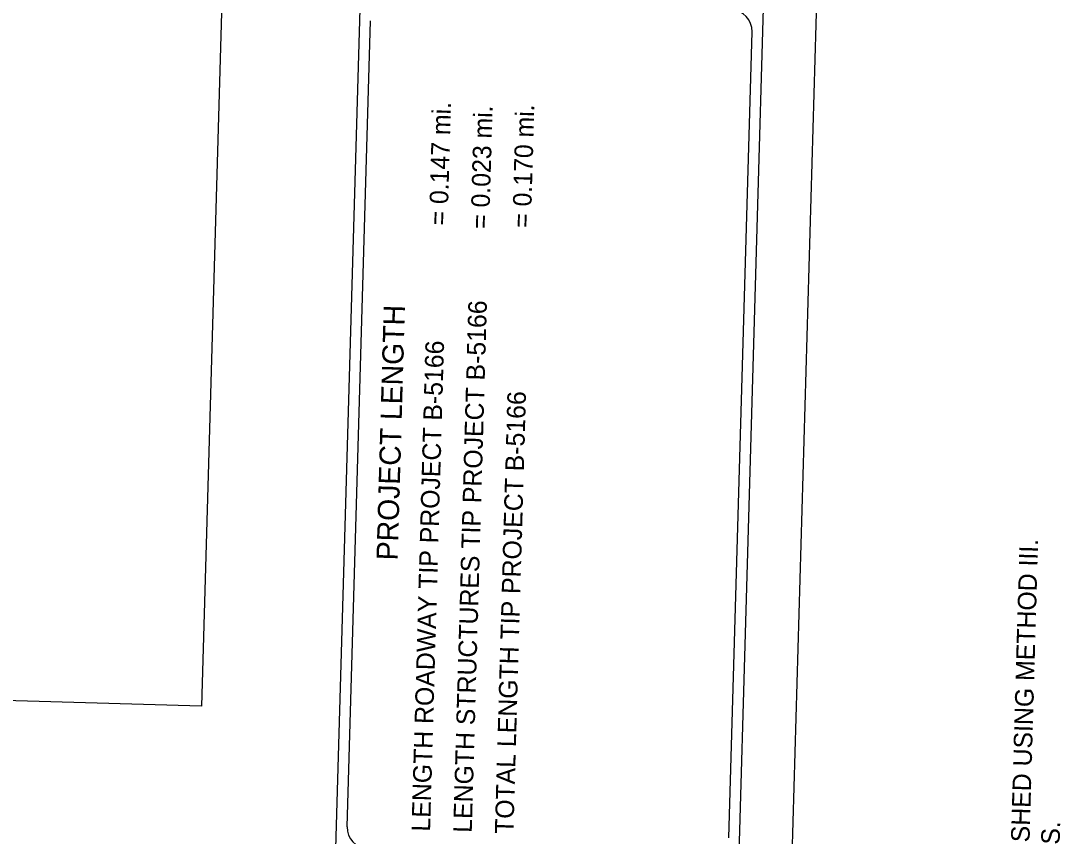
# Model space of a CAD drawing. Extents: x 2097846 to 2099709, y 989477 to 992073.
# Drawn here: x 2098974 to 2099709, y 990349 to 990925 of the extents above; entities that cross this region are included whole.
import ezdxf

# ---------------------------------------------------------------- set-up
doc = ezdxf.new("R2010")
doc.units = 0
for name, color, linetype in [('Sheet Data Field CELL', 7, 'Continuous'), ('Sheet Title CELL', 7, 'Continuous'), ('Stewart Plot Border Xerox6279 and LJ5000', 7, 'Continuous')]:
    doc.layers.add(name, color=color, linetype=linetype)

msp = doc.modelspace()

# ---------------------------------------------------------------- linework, layer by layer
at = {"layer": 'Sheet Title CELL'}
for p, q in [((2099183.04, 989845.97), (2099244.37, 991975.08)), ((2099205.24, 990355.54), (2099221.65, 990925.3))]:
    msp.add_line(p, q, dxfattribs=at)
for points in [[(2099465.57, 989755.3), (2099529.49, 991974.37)], [(2098625.54, 991828.82), (2099141.74, 991813.95), (2099102.18, 990440.79), (2098609.99, 990454.98)], [(2099475.13, 990347.77), (2099491.54, 990917.53)]]:
    msp.add_lwpolyline(points, dxfattribs=at)
for centre, start, end in [((2099476.46, 990917.97), 358.35004, 88.35004), ((2099220.15, 990355.12), 178.35004, 268.35004)]:
    msp.add_arc(centre, 15, start, end, dxfattribs=at)
at = {"layer": 'Stewart Plot Border Xerox6279 and LJ5000'}
msp.add_lwpolyline([(2099495.04, 989476.82), (2099568.48, 992025.76), (2097919.17, 992073.28), (2097845.72, 989524.34)], close=True, dxfattribs=at)

# ---------------------------------------------------------------- texts
at = {"layer": 'Sheet Data Field CELL'}
for s, p in [('= 0.147 mi.', (2099276.13, 990780.48)), ('= 0.170 mi.', (2099335.04, 990778.78)), ('= 0.023 mi.', (2099305.54, 990778.06)), ('LENGTH STRUCTURES TIP PROJECT B-5166', (2099293.24, 990351.19)), ('LENGTH ROADWAY TIP PROJECT B-5166', (2099263.78, 990352.04)), ('TOTAL LENGTH TIP PROJECT B-5166', (2099322.69, 990350.34)), ('CLEARING ON THIS PROJECT SHALL BE TO LIMITS ESTABLISHED USING METHOD III.', (2099672.96, 989835.55)), ('THIS PROJECT IS NOT WITHIN ANY MUNICIPAL BOUNDARIES.', (2099694.28, 989834.94))]:
    msp.add_text(s, height=13.125, rotation=88.35679, dxfattribs=at).set_placement(p)
at = {"layer": 'Sheet Title CELL'}
msp.add_text('PROJECT LENGTH', height=15, rotation=88.35004, dxfattribs=at).set_placement((2099240.88, 990543.74))

doc.saveas('drawing.dxf')
